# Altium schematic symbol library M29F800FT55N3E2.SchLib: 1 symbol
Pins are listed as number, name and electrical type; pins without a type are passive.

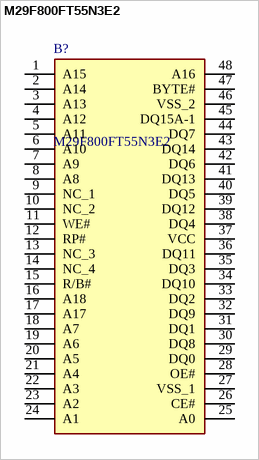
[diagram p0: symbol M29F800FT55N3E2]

## M29F800FT55N3E2
designator B?
NOR Flash NOR Flash(Micron) , PARALLEL, 8M , TSOP 48PIN, 55ns, -40-+125C, TOP, Tray; Manufacturer_Name: Alliance Memory; Geometry.Height: 1.2mm
footprint SOP50P2000X120-48N
pins: 1 A15, 2 A14, 3 A13, 4 A12, 5 A11, 6 A10, 7 A9, 8 A8, 9 NC_1, 10 NC_2, 11 WE#, 12 RP#, 13 NC_3, 14 NC_4, 15 R/B#, 16 A18, 17 A17, 18 A7, 19 A6, 20 A5, 21 A4, 22 A3, 23 A2, 24 A1, 25 A0, 26 CE#, 27 VSS_1, 28 OE#, 29 DQ0, 30 DQ8, 31 DQ1, 32 DQ9, 33 DQ2, 34 DQ10, 35 DQ3, 36 DQ11, 37 VCC, 38 DQ4, 39 DQ12, 40 DQ5, 41 DQ13, 42 DQ6, 43 DQ14, 44 DQ7, 45 DQ15A-1, 46 VSS_2, 47 BYTE#, 48 A16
